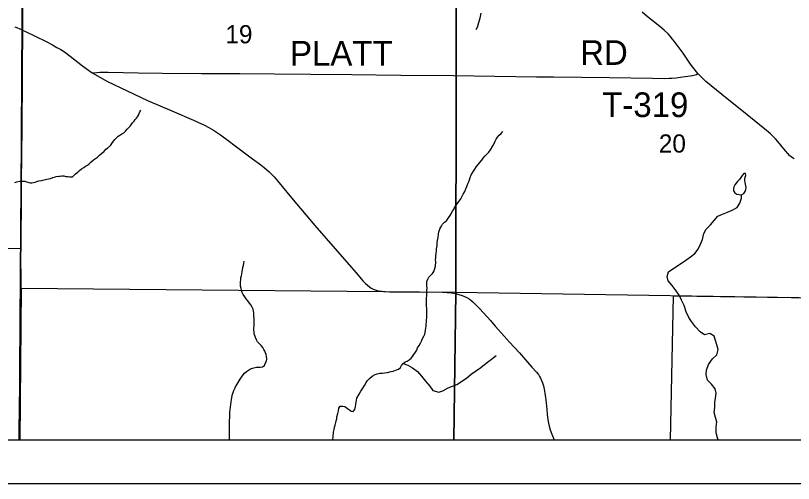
# Model space of a CAD drawing. Extents: x -8.8 to 41.4, y 0 to 34.6.
# Drawn here: x -5.453 to -3.661, y 14 to 15.077 of the extents above; entities that cross this region are included whole.
import ezdxf

# ---------------------------------------------------------------- set-up
doc = ezdxf.new("R2010")
doc.units = 0
for name, color, linetype in [('GM_X_Corporation', 7, 'Continuous'), ('GM_X_County_Road', 7, 'Continuous'), ('GM_X_Minor_Lake', 7, 'Continuous'), ('GM_X_Minor_River', 7, 'Continuous'), ('GM_X_Section_Text', 7, 'Continuous'), ('GM_X_Township_Road', 7, 'Continuous'), ('GM_X_Township_Text', 7, 'Continuous'), ('SH_Border', 7, 'Continuous')]:
    doc.layers.add(name, color=color, linetype=linetype)

msp = doc.modelspace()

# ---------------------------------------------------------------- linework, layer by layer
at = {"layer": 'GM_X_Corporation'}
for points in [[(-8.6743, 18.6925), (-8.6743, 14.1), (-5.4442, 14.1), (-5.4432, 14.2265), (-5.4429, 14.2618), (-5.4404, 14.5882), (-5.4368, 15.0446), (-5.435, 15.3164), (-5.4282, 16.3507), (-5.4212, 16.5483), (-5.4129, 17.3836), (-5.4008, 18.6369)], [(-5.4008, 18.6369), (-5.4129, 17.3836), (-5.4212, 16.5483), (-5.4282, 16.3507), (-5.435, 15.3164), (-5.4368, 15.0446), (-5.4404, 14.5882), (-5.4429, 14.2618), (-5.4432, 14.2265), (-5.4442, 14.1), (-1.8743, 14.1), (-1.8743, 18.5906)]]:
    msp.add_lwpolyline(points, dxfattribs=at)
for points in [[(-6.4479, 15.5667), (-5.4349, 15.5503), (-5.4351, 15.4586), (-5.4406, 14.5401), (-6.4506, 14.5538)], [(-5.4351, 15.4586), (-4.4369, 15.4422), (-4.4383, 14.4395), (-5.4401, 14.4488), (-5.4406, 14.5401)], [(-4.4369, 15.4422), (-3.4436, 15.4293), (-3.4507, 14.4245), (-4.4383, 14.4395)], [(-6.4536, 14.1), (-5.4429, 14.1), (-5.4401, 14.4488), (-5.4406, 14.5401), (-6.4506, 14.5538)], [(-5.4429, 14.1), (-4.443, 14.1), (-4.4383, 14.4395), (-5.4401, 14.4488)], [(-4.443, 14.1), (-3.4536, 14.1), (-3.4507, 14.4245), (-4.4383, 14.4395)], [(-3.9447, 14.1), (-3.4526, 14.1), (-3.4525, 14.1076), (-3.4509, 14.2324), (-3.4492, 14.3764), (-3.4488, 14.4247), (-3.938, 14.4315)]]:
    msp.add_lwpolyline(points, close=True, dxfattribs=at)
at = {"layer": 'GM_X_County_Road'}
for points in [[(-5.4442, 14.1), (-5.4441, 14.1222), (-5.4429, 14.2259), (-5.4428, 14.2378), (-5.4427, 14.2612), (-5.4421, 14.3474), (-5.4417, 14.4306), (-5.4405, 14.5496), (-5.4401, 14.5876), (-5.4394, 14.6539), (-5.4389, 14.6999), (-5.4385, 14.7507), (-5.4377, 14.8278), (-5.4369, 14.9246), (-5.4364, 14.9991), (-5.4364, 15.0351), (-5.4366, 15.044), (-5.4369, 15.0557), (-5.4367, 15.0904)], [(-3.6592, 14.7478), (-3.6618, 14.7492), (-3.6654, 14.7515), (-3.6699, 14.7553), (-3.674, 14.7598), (-3.6794, 14.7658), (-3.6871, 14.7753), (-3.6969, 14.7874), (-3.7022, 14.7936), (-3.7066, 14.7981), (-3.7138, 14.8049), (-3.7229, 14.8126), (-3.7675, 14.8485), (-3.8259, 14.8956), (-3.8629, 14.926), (-3.8707, 14.933), (-3.8812, 14.9442), (-3.8843, 14.9481), (-3.8977, 14.9659), (-3.9152, 14.9909), (-3.9356, 15.0183), (-3.9393, 15.0232), (-3.945, 15.03), (-3.9495, 15.0351), (-3.9588, 15.0435), (-3.969, 15.0524), (-3.9977, 15.0755), (-4.0091, 15.0853)], [(-5.4544, 15.0515), (-5.4483, 15.0493), (-5.4446, 15.0479), (-5.4399, 15.0457), (-5.4366, 15.044)], [(-5.4366, 15.044), (-5.4295, 15.0406), (-5.4077, 15.0304), (-5.3825, 15.0176), (-5.3676, 15.0099), (-5.3573, 15.0042), (-5.3488, 14.9991), (-5.3402, 14.9937), (-5.3273, 14.9842), (-5.2982, 14.9617), (-5.2762, 14.9456), (-5.241, 14.926), (-5.1957, 14.904), (-5.149, 14.882), (-5.0931, 14.8579), (-5.0426, 14.8362), (-5.0247, 14.8283), (-5.0175, 14.8249), (-5.0076, 14.8197), (-4.9969, 14.8135), (-4.9896, 14.8089), (-4.9804, 14.8025), (-4.9629, 14.7897), (-4.9466, 14.7772), (-4.9283, 14.7633), (-4.9068, 14.7475), (-4.8879, 14.7334), (-4.8801, 14.7273), (-4.8687, 14.7177), (-4.8625, 14.7117), (-4.857, 14.7059), (-4.8493, 14.697), (-4.8168, 14.6578), (-4.7631, 14.5941), (-4.7166, 14.5406), (-4.6889, 14.5087), (-4.6638, 14.4795), (-4.6528, 14.4669), (-4.6468, 14.4605), (-4.6422, 14.4562), (-4.6378, 14.4526), (-4.6335, 14.4499), (-4.629, 14.4476), (-4.6243, 14.4458), (-4.6195, 14.4443), (-4.614, 14.4431), (-4.609, 14.4424), (-4.6015, 14.4418), (-4.5903, 14.4414), (-4.5549, 14.4411), (-4.4694, 14.4403), (-4.4589, 14.4397), (-4.4489, 14.4388), (-4.4398, 14.4374), (-4.4316, 14.4353), (-4.4243, 14.4329), (-4.4185, 14.4307), (-4.413, 14.428), (-4.4082, 14.4252), (-4.4037, 14.422), (-4.3991, 14.4181), (-4.3946, 14.4138), (-4.3836, 14.4022), (-4.3589, 14.3749), (-4.3476, 14.3621), (-4.3331, 14.346), (-4.3154, 14.3264), (-4.2922, 14.3004), (-4.2733, 14.2794), (-4.2634, 14.2679), (-4.2531, 14.2563), (-4.2485, 14.2505), (-4.2455, 14.2459), (-4.2434, 14.2421), (-4.241, 14.2372), (-4.2388, 14.2314), (-4.2368, 14.225), (-4.235, 14.2172), (-4.2333, 14.208), (-4.232, 14.1976), (-4.2308, 14.1859), (-4.2293, 14.1704), (-4.2282, 14.1593), (-4.2265, 14.1464), (-4.225, 14.1384), (-4.2234, 14.1317), (-4.2209, 14.1233), (-4.2162, 14.1098), (-4.2124, 14.1)]]:
    msp.add_lwpolyline(points, dxfattribs=at)
at = {"layer": 'GM_X_Minor_Lake'}
msp.add_line((-3.7914, 14.6665), (-3.7804, 14.6643), dxfattribs=at)
msp.add_lwpolyline([(-3.7804, 14.6643), (-3.7754, 14.6675), (-3.7722, 14.672), (-3.7702, 14.6769), (-3.7697, 14.6814), (-3.7703, 14.6853), (-3.7724, 14.6929), (-3.773, 14.6979), (-3.7729, 14.7017), (-3.7717, 14.7054), (-3.7708, 14.7092), (-3.771, 14.7138), (-3.7752, 14.7139), (-3.7791, 14.7091), (-3.7855, 14.7001), (-3.7894, 14.6953), (-3.7925, 14.6916), (-3.7961, 14.6875), (-3.7985, 14.683), (-3.7993, 14.6792), (-3.7991, 14.6739), (-3.7958, 14.6696), (-3.7914, 14.6665)], dxfattribs=at)
at = {"layer": 'GM_X_Minor_River'}
for points in [[(-4.3807, 15.0832), (-4.3834, 15.0711), (-4.3863, 15.0609), (-4.3896, 15.05), (-4.3928, 15.0444)], [(-5.3534, 14.7076), (-5.35, 14.7079), (-5.3462, 14.7082), (-5.3416, 14.7081), (-5.3367, 14.7072), (-5.3326, 14.7067), (-5.3288, 14.7058), (-5.3254, 14.7057), (-5.3216, 14.7064), (-5.318, 14.7097), (-5.3146, 14.7126), (-5.3095, 14.717), (-5.3056, 14.7204), (-5.3006, 14.7244), (-5.2952, 14.7277), (-5.2913, 14.7306), (-5.2867, 14.7327), (-5.2832, 14.7357), (-5.2796, 14.7398), (-5.2734, 14.7453), (-5.2637, 14.7515), (-5.2594, 14.7563), (-5.2536, 14.7614), (-5.2494, 14.764), (-5.2446, 14.7696), (-5.2408, 14.7721), (-5.2334, 14.7791), (-5.2306, 14.7832), (-5.2274, 14.7884), (-5.2243, 14.7918), (-5.2204, 14.7962), (-5.2161, 14.7995), (-5.2126, 14.8017), (-5.2076, 14.8054), (-5.2037, 14.8075), (-5.1998, 14.8116), (-5.1959, 14.8161), (-5.1889, 14.8227), (-5.1865, 14.8261), (-5.1833, 14.8301), (-5.1798, 14.8346), (-5.1771, 14.8379), (-5.1739, 14.8413), (-5.1716, 14.8446), (-5.1699, 14.848), (-5.1683, 14.8518), (-5.1663, 14.8555), (-5.1639, 14.8596)], [(-4.4854, 14.5002), (-4.485, 14.51), (-4.4852, 14.515), (-4.4847, 14.5203), (-4.4845, 14.5245), (-4.484, 14.5294), (-4.4834, 14.5358), (-4.4828, 14.5404), (-4.4818, 14.5476), (-4.4816, 14.5544), (-4.4806, 14.5597), (-4.4796, 14.5662), (-4.4786, 14.5737), (-4.4777, 14.5794), (-4.4764, 14.5836), (-4.4747, 14.5877), (-4.4719, 14.5926), (-4.4691, 14.5967), (-4.4645, 14.6015), (-4.4598, 14.6051), (-4.4555, 14.6119), (-4.4519, 14.6167), (-4.4495, 14.6212), (-4.4467, 14.6261), (-4.4435, 14.6309), (-4.4414, 14.6358), (-4.4371, 14.6418), (-4.4339, 14.6462), (-4.4312, 14.6503), (-4.4272, 14.6555), (-4.424, 14.6619), (-4.4216, 14.6664), (-4.4176, 14.6724), (-4.4155, 14.6784), (-4.4134, 14.6841), (-4.4114, 14.6882), (-4.4097, 14.6931), (-4.4068, 14.6995), (-4.4055, 14.7044), (-4.4031, 14.7104), (-4.4003, 14.7149), (-4.3979, 14.719), (-4.3947, 14.7238), (-4.3907, 14.7298), (-4.3789, 14.7443), (-4.3754, 14.7491), (-4.3715, 14.7536), (-4.3672, 14.7584), (-4.3629, 14.7628), (-4.3589, 14.7681), (-4.3533, 14.7778), (-4.3505, 14.783), (-4.3481, 14.7879), (-4.3456, 14.7932), (-4.3425, 14.7976), (-4.3389, 14.8021), (-4.3343, 14.8061), (-4.3303, 14.8106)], [(-5.4547, 14.6934), (-5.4498, 14.6948), (-5.4429, 14.6961), (-5.4387, 14.6964), (-5.4345, 14.6962), (-5.4311, 14.6958), (-5.4274, 14.6945), (-5.4191, 14.692), (-5.4153, 14.6923), (-5.4111, 14.6929), (-5.4073, 14.694), (-5.4038, 14.6954), (-5.3992, 14.6968), (-5.3924, 14.6977), (-5.387, 14.6991), (-5.3809, 14.7004), (-5.3767, 14.7011), (-5.3725, 14.7025), (-5.3668, 14.7046), (-5.3629, 14.7056), (-5.3591, 14.7067), (-5.3534, 14.7076)], [(-3.8342, 14.1), (-3.8355, 14.1047), (-3.8386, 14.1162), (-3.8386, 14.1295), (-3.8371, 14.1416), (-3.8402, 14.1516), (-3.8433, 14.1631), (-3.8423, 14.1748), (-3.8416, 14.1862), (-3.8401, 14.196), (-3.839, 14.2082), (-3.8414, 14.2181), (-3.8495, 14.2286), (-3.8591, 14.238), (-3.8621, 14.251), (-3.8611, 14.2608), (-3.8566, 14.274), (-3.8471, 14.2867), (-3.8374, 14.2959), (-3.8344, 14.3083), (-3.8371, 14.319), (-3.8402, 14.3294), (-3.8437, 14.3394), (-3.8534, 14.345), (-3.866, 14.3423), (-3.8761, 14.3494), (-3.8864, 14.3607), (-3.8955, 14.3727), (-3.9021, 14.3824), (-3.9082, 14.3955), (-3.9127, 14.4097), (-3.9188, 14.4217), (-3.9242, 14.4336), (-3.9307, 14.4436), (-3.9406, 14.4561), (-3.9491, 14.4666), (-3.9518, 14.4765), (-3.9489, 14.4875), (-3.9361, 14.4958), (-3.9234, 14.5038), (-3.9091, 14.5141), (-3.8978, 14.5221), (-3.8881, 14.5298), (-3.8806, 14.5395), (-3.875, 14.5507), (-3.8705, 14.562), (-3.8671, 14.5755), (-3.8619, 14.5857), (-3.8518, 14.5952), (-3.8431, 14.6056), (-3.8353, 14.6153), (-3.8245, 14.6203), (-3.8126, 14.6249), (-3.8019, 14.6295), (-3.7907, 14.6353), (-3.784, 14.6457), (-3.7802, 14.657), (-3.7804, 14.6643)], [(-4.9033, 14.362), (-4.903, 14.3715), (-4.9032, 14.3776), (-4.9036, 14.3875), (-4.9038, 14.392), (-4.9047, 14.397), (-4.9057, 14.4016), (-4.9074, 14.4058), (-4.9106, 14.4112), (-4.9138, 14.4155), (-4.9174, 14.4202), (-4.9214, 14.4252), (-4.9246, 14.4299), (-4.9285, 14.435), (-4.931, 14.4396), (-4.9323, 14.4446), (-4.9333, 14.4488), (-4.9342, 14.4545), (-4.9348, 14.4595), (-4.9343, 14.4644), (-4.9341, 14.4686), (-4.9336, 14.4731), (-4.9326, 14.4784), (-4.9317, 14.483), (-4.9308, 14.4871), (-4.9299, 14.492), (-4.9289, 14.4973), (-4.928, 14.5015), (-4.9271, 14.5072), (-4.9265, 14.5117)], [(-4.7218, 14.1), (-4.7217, 14.1015), (-4.7211, 14.1076), (-4.72, 14.1182), (-4.7187, 14.1239), (-4.7177, 14.1296), (-4.7164, 14.1345), (-4.7151, 14.1401), (-4.7142, 14.1443), (-4.7129, 14.1488), (-4.7124, 14.1537), (-4.7102, 14.1613), (-4.7092, 14.1673), (-4.7079, 14.1734), (-4.7047, 14.1782), (-4.6991, 14.1781), (-4.6942, 14.1768), (-4.688, 14.1724), (-4.6836, 14.1693), (-4.6796, 14.1665), (-4.6751, 14.1656), (-4.6712, 14.1704), (-4.6694, 14.1772), (-4.6689, 14.1814), (-4.6679, 14.1871), (-4.6674, 14.1916), (-4.6665, 14.1962), (-4.6613, 14.2059), (-4.6573, 14.2126), (-4.6529, 14.2193), (-4.6489, 14.2253), (-4.6453, 14.2321), (-4.6425, 14.2365), (-4.6374, 14.2413), (-4.6309, 14.2469), (-4.6247, 14.2505), (-4.6194, 14.2526), (-4.6133, 14.2536), (-4.6077, 14.2542), (-4.6028, 14.2548), (-4.5963, 14.2557), (-4.5873, 14.2578), (-4.5831, 14.2588), (-4.5751, 14.2616), (-4.5705, 14.2634), (-4.5659, 14.267), (-4.5635, 14.2715), (-4.5599, 14.2764), (-4.5553, 14.2797), (-4.5503, 14.2814), (-4.5457, 14.2847), (-4.5411, 14.2884), (-4.5383, 14.2925), (-4.5351, 14.297), (-4.5315, 14.3026), (-4.5287, 14.307), (-4.5267, 14.3119), (-4.5231, 14.3179), (-4.5199, 14.3231), (-4.5175, 14.3273), (-4.5158, 14.3325), (-4.5122, 14.3393), (-4.5102, 14.3434), (-4.5089, 14.3475), (-4.5083, 14.3532), (-4.5078, 14.3574), (-4.5072, 14.362), (-4.5067, 14.3673), (-4.5065, 14.3722), (-4.506, 14.3764), (-4.5054, 14.3813), (-4.5051, 14.39), (-4.5053, 14.3961), (-4.5055, 14.4011), (-4.5059, 14.4102), (-4.5061, 14.4152), (-4.505, 14.4444), (-4.5048, 14.4497), (-4.505, 14.4551), (-4.5056, 14.4597), (-4.5051, 14.465), (-4.503, 14.4702), (-4.5006, 14.4747), (-4.4959, 14.4795), (-4.4924, 14.4836), (-4.4896, 14.4881), (-4.4867, 14.4952), (-4.4854, 14.5002)], [(-4.9598, 14.1), (-4.9599, 14.1046), (-4.96, 14.1129), (-4.9601, 14.119), (-4.9603, 14.1247), (-4.9601, 14.1301), (-4.9603, 14.135), (-4.9599, 14.1457), (-4.9594, 14.151), (-4.9589, 14.165), (-4.9584, 14.1692), (-4.9578, 14.1753), (-4.9558, 14.1881), (-4.9553, 14.1923), (-4.9543, 14.198), (-4.9529, 14.2052), (-4.9517, 14.2093), (-4.95, 14.2138), (-4.9479, 14.2183), (-4.9459, 14.2225), (-4.9423, 14.2288), (-4.9351, 14.24), (-4.9324, 14.2445), (-4.9288, 14.2497), (-4.9252, 14.2542), (-4.921, 14.2579), (-4.916, 14.2612), (-4.9118, 14.2637), (-4.9072, 14.2658), (-4.8981, 14.2679), (-4.8891, 14.2676), (-4.8842, 14.2682), (-4.8795, 14.2719), (-4.8775, 14.2764), (-4.875, 14.2816), (-4.8741, 14.2866), (-4.8747, 14.2923), (-4.8756, 14.2969), (-4.8784, 14.3042), (-4.8805, 14.3084), (-4.8833, 14.3131), (-4.8869, 14.3177), (-4.8916, 14.3221), (-4.8952, 14.3264), (-4.8977, 14.331), (-4.9001, 14.336), (-4.9028, 14.3445), (-4.9034, 14.349), (-4.9037, 14.3532), (-4.9035, 14.3574), (-4.9033, 14.362)], [(-4.5599, 14.2764), (-4.5495, 14.2725), (-4.5387, 14.2662), (-4.5272, 14.2579), (-4.518, 14.2473), (-4.5084, 14.2357), (-4.4982, 14.2236), (-4.4912, 14.2139), (-4.478, 14.2101), (-4.4685, 14.2133), (-4.4565, 14.2205), (-4.4465, 14.224), (-4.4366, 14.2279), (-4.4254, 14.2348), (-4.413, 14.2432), (-4.4029, 14.2513), (-4.3929, 14.2582), (-4.3812, 14.2666), (-4.3684, 14.2773), (-4.3564, 14.2861), (-4.3455, 14.2949)]]:
    msp.add_lwpolyline(points, dxfattribs=at)
at = {"layer": 'GM_X_Township_Road'}
msp.add_lwpolyline([(-5.2762, 14.9456), (-5.2653, 14.9467), (-5.2586, 14.9472), (-5.2396, 14.9468), (-5.1706, 14.9458), (-5.1147, 14.9451), (-5.0245, 14.9443), (-4.936, 14.9443), (-4.8564, 14.9431), (-4.7727, 14.9423), (-4.6785, 14.9416), (-4.5654, 14.9402), (-4.4436, 14.9392), (-4.3489, 14.938), (-4.2524, 14.9366), (-4.2134, 14.9365), (-4.0842, 14.9349), (-3.9854, 14.9334), (-3.9587, 14.9328), (-3.9469, 14.933), (-3.9407, 14.9334), (-3.9308, 14.9343), (-3.9167, 14.936), (-3.9038, 14.9378), (-3.8934, 14.9394), (-3.8874, 14.9409), (-3.8844, 14.942), (-3.8812, 14.9442)], dxfattribs=at)
at = {"layer": 'SH_Border'}
for p, q in [((-8.6743, 14.1), (-1.8743, 14.1)), ((-8.7743, 14), (-1.7743, 14))]:
    msp.add_line(p, q, dxfattribs=at)

# ---------------------------------------------------------------- texts
at = {"layer": 'GM_X_Section_Text'}
for s, p in [('PLATT', (-4.8205, 14.9623)), ('RD', (-4.1522, 14.9639)), ('T-319', (-4.1014, 14.8437))]:
    msp.add_text(s, height=0.05682, rotation=0, dxfattribs=at).set_placement(p)
at = {"layer": 'GM_X_Township_Text'}
for s, p in [('19', (-4.9693, 15.0136)), ('20', (-3.9709, 14.7619))]:
    msp.add_text(s, height=0.04186, rotation=0, dxfattribs=at).set_placement(p)

doc.saveas('drawing.dxf')
